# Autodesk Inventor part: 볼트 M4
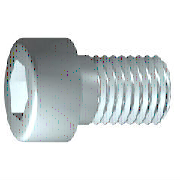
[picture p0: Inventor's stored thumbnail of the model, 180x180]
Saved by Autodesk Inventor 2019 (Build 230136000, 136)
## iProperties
IsCustomPart: 0
Created: 2012-02
Part Number: 볼트 M4
Material: 스테인리스강
Description: 6각 소켓 머리 캡 나사
Document SubType Name: Modeling
Standard: ISO 4762
Designer: mduedu
Standard Revision: Fourth edition 2004-03-01
Standards Organization: ISO
Language: ko-KR
Size Designation: M4 x 10
Categories: <MemberInstance><Categories><Category DisplayName="조임쇠" InternalName="e4da775c-781d-43d5-af7c-5136215cf5a6" Mnemonic="FSTN"><Category DisplayName="볼트" InternalN
Density: 8.08 g/cm^3
Appearance: 반광택
Author: mduedu
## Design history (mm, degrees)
sketch "스케치1"
  geometry: L1 (-1, 0)-(10, 0); L2 (10, 0)-(10, 2); L3 (10, 2)-(1.75, 2); L4 (1.75, 2)-(1.32, 2); L5 (1.32, 2)-(0, 2); L6 (0, 2)-(0, 3.5); L7 (0, 3.5)-(-4, 3.5); L8 (-4, 3.5)-(-4, 1.732); L9 (-4, 1.732)-(-2, 1.732); L10 (-2, 1.732)-(-1, 0); L11 (-6.8, 0)-(12.8, 0) reference; L12 (0, -0.7)-(0, 4.2) reference; L13 (1.75, 2)-(0, 2)
  constraints: 22 end point, 6 parallel, 2 collinear, 2 perpendicular, 1 horizontal, 1 point on line
  dimensions: "d1" = 8.25 distance from line of L3.end L2 (= GEL); "d2" = 0.42952 distance of L4.end L3.end (computed from GAL); "d3" = 4 distance between parallel lines of L8 L6 (= KOH); "d4" = 2 distance of L8.end L9.end (= INTI); "d5" = 60 deg angle of L10 L1; "d6" = 4 diameter of L3 L1 (= GD); "d7" = 4 diameter of L5 L1 (= BDM); "d8" = 3.4641 diameter of L9 L1 (= 1.1547 x SW); "d9" = 7 diameter of L7 L1 (= KOD); "d26" = 10 distance between parallel lines of L12 L2 (= NLG)
revolve "본체" sketch "스케치1" stored, may be unused: angle "d10" = 90 deg
sketch "스케치2"
  geometry: L1 (0, -4.9)-(0, 4.9) reference; L2 (-4.9, 0)-(4.9, 0) reference; L3 (1.732, 0)-(0.866, -1.5); L4 (0.866, -1.5)-(-0.866, -1.5); L5 (-0.866, -1.5)-(-1.732, 0); L6 (-1.732, 0)-(-0.866, 1.5); L7 (-0.866, 1.5)-(0.866, 1.5); L8 (0.866, 1.5)-(1.732, 0); 2 further points
  constraints: 12 end point, 1 coincident, 1 horizontal alignment, 1 point on line, 12 other
extrude "슬롯" join sketch "스케치2" stored distance "d11" = 10; taper "d12" = 0 deg
workplane "Work Plane1"
fillet "Fillet2" dims "d30" = 0.1 (= R)
body "Solid1"
fillet "모깎기1" dims "d17" = 0.4 (= RR)
feature "스레드" dims "d13" = 8.25 (= GEL), "d14" = 0
chamfer "모따기1" distance "d15" = 0.42941 (= -0.5 x SPD + 0.5 x GD); stored, may be unused: second distance "d16" = 0.42941 (= GUL), angle "d27" = 45 deg
other parameters: "GD" = 4 [user parameter; used in 2 equation terms], "NLG" = 10 [user parameter; used in 1 equation term], "GEL" = 8.25 [user parameter; used in 2 equation terms], "KOD" = 7 [user parameter; used in 1 equation term], "KOH" = 4 [user parameter; used in 1 equation term], "INTI" = 2 [user parameter; used in 1 equation term], "GAL" = 0.42941 (= 0.61345 x PTC) [user parameter; used in 1 equation term], "GUL" = 0.42941 (= 0.61345 x PTC) [user parameter; used in 1 equation term], "BDM" = 4 (= NND) [user parameter; used in 1 equation term], "SW" = 3 [user parameter; used in 2 equation terms], "RR" = 0.4 [user parameter; used in 1 equation term], "SPD" = 3.14117 (= NND - 1.2269 x PTC) [user parameter; used in 1 equation term], "d19" = 0, "d28" = 0, "d29" = 0, "R" = 0.1 [user parameter; used in 1 equation term], "TOA" = 30 deg [user parameter], "GD1" = 3.14117 (= THREADDIA - 1.2269 x PTC) [user parameter], "THREADDIA" = 4 [user parameter; used in 1 equation term], "FAWI" = 45 deg [user parameter], "TPU" = 14.28571 (computed from PTC) [user parameter], "PTC" = 0.7 [user parameter; used in 5 equation terms], "NND" = 4 [user parameter; used in 2 equation terms], "E0" = 3.465 (= 1.155 x SW) [user parameter]
